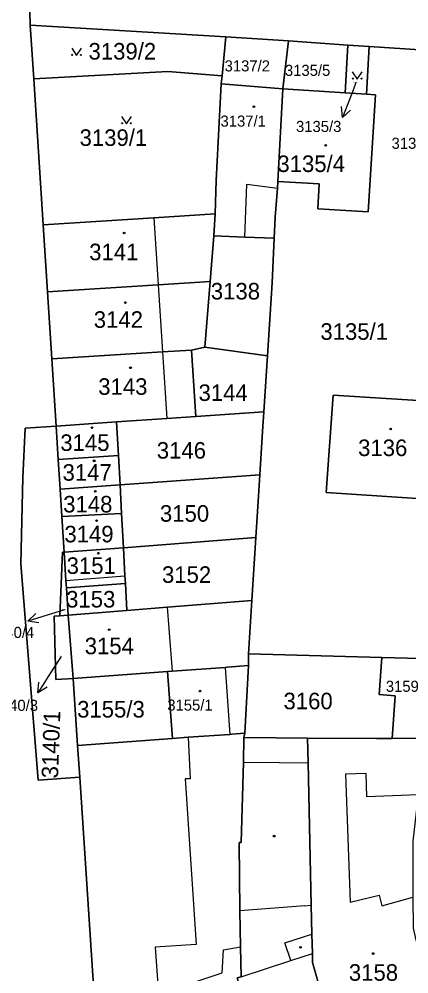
# Model space of a CAD drawing. Extents: x -596233 to -595156, y -1161235 to -1159375.
# Drawn here: x -595617.7 to -595577.7, y -1161038.8 to -1160940.7 of the extents above; entities that cross this region are included whole.
import ezdxf

# ---------------------------------------------------------------- set-up
doc = ezdxf.new("R2010")
doc.units = 0
for name, color, linetype in [('KN_CAR_KR', 7, 'Continuous'), ('KN_KULTURY', 7, 'Continuous'), ('KN_PARC_CIS_POM', 7, 'Continuous'), ('KN_PARC_CIS_POZ', 7, 'Continuous'), ('KN_PARC_CIS_STAV', 7, 'Continuous'), ('KN_PARC_PLOCHA', 7, 'Continuous'), ('PARC_C_SIPKA', 7, 'Continuous'), ('parcely_l', 7, 'Continuous')]:
    doc.layers.add(name, color=color, linetype=linetype)

msp = doc.modelspace()

# ---------------------------------------------------------------- linework, layer by layer
at = {"layer": 'KN_CAR_KR'}
for points in [[(-595594.53, -1160963.12), (-595594.34, -1160957.7)], [(-595594.34, -1160957.7), (-595591.19, -1160958.09)], [(-595603.88, -1160961.14), (-595603.44, -1160968.03)], [(-595603.44, -1160968.03), (-595603, -1160974.92)], [(-595603, -1160974.92), (-595602.57, -1160981.75)], [(-595612.93, -1160998.39), (-595606.86, -1160997.92)], [(-595602.52, -1161001.14), (-595602.01, -1161007.7)], [(-595596.56, -1161007.33), (-595596.08, -1161014.2)], [(-595600.35, -1161014.49), (-595600.16, -1161018.74)], [(-595594.67, -1161017.04), (-595591.02, -1161017.08)], [(-595591.02, -1161017.08), (-595588.04, -1161017.11)], [(-595600.16, -1161018.74), (-595600.66, -1161018.77)], [(-595600.66, -1161018.77), (-595599.55, -1161035.76)], [(-595582.08, -1161018.2), (-595584.21, -1161018.28)], [(-595584.21, -1161018.28), (-595583.71, -1161031.42)], [(-595581.99, -1161020.61), (-595582.08, -1161018.2)], [(-595576.71, -1161020.41), (-595581.99, -1161020.61)], [(-595583.71, -1161031.42), (-595580.74, -1161030.7)], [(-595580.74, -1161030.7), (-595580.45, -1161031.8)], [(-595580.45, -1161031.8), (-595577.28, -1161030.89)], [(-595588.38, -1161031.78), (-595595.05, -1161032.3)], [(-595588.38, -1161031.78), (-595587.71, -1161031.73)], [(-595590.42, -1161035.6), (-595588.52, -1161034.98)], [(-595588.52, -1161034.98), (-595587.64, -1161034.69)], [(-595599.55, -1161035.76), (-595603.74, -1161036.04)], [(-595603.74, -1161036.04), (-595603.42, -1161040.86)], [(-595596.86, -1161038.66), (-595596.75, -1161036.32)], [(-595596.75, -1161036.32), (-595594.98, -1161036)], [(-595589.82, -1161037.41), (-595590.42, -1161035.6)], [(-595594.92, -1161039.08), (-595589.82, -1161037.41)], [(-595589.82, -1161037.41), (-595587.6, -1161036.68)], [(-595603.42, -1161040.86), (-595596.86, -1161038.66)]]:
    msp.add_lwpolyline(points, dxfattribs=at)
at = {"layer": 'KN_KULTURY'}
for points in [[(-595612.3318, -1160943.7116), (-595611.8318, -1160944.4616), (-595611.3318, -1160943.7116)], [(-595583.4918, -1160946.1516), (-595582.9918, -1160946.9016), (-595582.4918, -1160946.1516)], [(-595607.2018, -1160950.7316), (-595606.7018, -1160951.4816), (-595606.2018, -1160950.7316)]]:
    msp.add_lwpolyline(points, dxfattribs=at)
for centre, radius in [((-595612.282, -1160944.4114), 0.05), ((-595611.3826, -1160944.4114), 0.05), ((-595583.442, -1160946.8514), 0.05), ((-595582.5426, -1160946.8514), 0.05), ((-595593.61, -1160949.73), 0.09), ((-595593.61, -1160949.73), 0.0398), ((-595607.152, -1160951.4314), 0.05), ((-595606.2526, -1160951.4314), 0.05), ((-595586.23, -1160953.7), 0.09), ((-595586.23, -1160953.7), 0.0398), ((-595606.95, -1160962.7), 0.09), ((-595606.95, -1160962.7), 0.0398), ((-595606.82, -1160969.85), 0.09), ((-595606.82, -1160969.85), 0.0398), ((-595606.29, -1160976.54), 0.09), ((-595606.29, -1160976.54), 0.0398), ((-595610.25, -1160982.69), 0.09), ((-595610.25, -1160982.69), 0.0398), ((-595579.55, -1160982.83), 0.09), ((-595579.55, -1160982.83), 0.0398), ((-595610.03, -1160986.1), 0.09), ((-595610.03, -1160986.1), 0.0398), ((-595609.91, -1160989.23), 0.09), ((-595609.91, -1160989.23), 0.0398), ((-595609.77, -1160992.24), 0.09), ((-595609.77, -1160992.24), 0.0398), ((-595609.6, -1160995.59), 0.09), ((-595609.6, -1160995.59), 0.0398), ((-595608.48, -1161003.44), 0.09), ((-595608.48, -1161003.44), 0.0398), ((-595599.15, -1161009.74), 0.09), ((-595599.15, -1161009.74), 0.0398), ((-595591.53, -1161024.63), 0.09), ((-595591.53, -1161024.63), 0.0398), ((-595588.83, -1161036.06), 0.09), ((-595588.83, -1161036.06), 0.0398), ((-595581.34, -1161036.7), 0.09), ((-595581.34, -1161036.7), 0.0398)]:
    msp.add_circle(centre, radius, dxfattribs=at)
at = {"layer": 'KN_PARC_PLOCHA'}
for points in [[(-595631.7, -1160897.5), (-595615.14, -1160895.31), (-595616.98, -1160898.71), (-595617.7, -1160902.65), (-595617.29, -1160919.81), (-595617.05, -1160922.72), (-595616.62, -1160941.37), (-595616.22, -1160946.87), (-595615.26, -1160961.87), (-595614.82, -1160968.76), (-595614.38, -1160975.64), (-595613.94, -1160982.53), (-595617.11, -1160982.74), (-595617.35, -1160987.8), (-595617.56, -1160996.69), (-595615.79, -1161018.89), (-595611.5, -1161018.59), (-595609.88, -1161043.14), (-595608.93, -1161050.44), (-595606.83, -1161051.74), (-595620.07, -1161056.19)], [(-595495.5, -1160949.29), (-595504.84, -1160948.66), (-595517.47, -1160947.9), (-595523.68, -1160947.4), (-595529.26, -1160947.06), (-595534.17, -1160946.74), (-595542.8, -1160946.18), (-595552.41, -1160945.52), (-595558.17, -1160945.14), (-595567.75, -1160944.5), (-595571.42, -1160944.26), (-595576.02, -1160943.94), (-595581.75, -1160943.55), (-595583.96, -1160943.4), (-595590.05, -1160942.98), (-595596.48, -1160942.57), (-595616.62, -1160941.37), (-595617.05, -1160922.72)], [(-595575.23, -1161006.44), (-595580.46, -1161006.3), (-595594.18, -1161005.93), (-595593.83, -1161000.44), (-595593.42, -1160993.98), (-595593.14, -1160989.72), (-595593, -1160987.53), (-595592.72, -1160983.09), (-595592.59, -1160981.07), (-595592.22, -1160975.31), (-595591.73, -1160967.81), (-595591.54, -1160963.24), (-595591.41, -1160961.08), (-595591.19, -1160958.09), (-595591.15, -1160957.4), (-595586.89, -1160957.66), (-595587.03, -1160960.22), (-595581.85, -1160960.53), (-595581.11, -1160948.52), (-595582.04, -1160948.46), (-595581.75, -1160943.55), (-595576.02, -1160943.94)], [(-595573.47, -1160980.12), (-595585.46, -1160979.35), (-595586.17, -1160989.36), (-595574.24, -1160990.15)]]:
    msp.add_lwpolyline(points, dxfattribs=at)
for points in [[(-595596.48, -1160942.57), (-595596.88, -1160946.56), (-595602.44, -1160946.12), (-595616.22, -1160946.87), (-595616.62, -1160941.37)], [(-595590.05, -1160942.98), (-595590.63, -1160947.91), (-595596.96, -1160947.37), (-595596.88, -1160946.56), (-595596.48, -1160942.57)], [(-595583.96, -1160943.4), (-595584.24, -1160948.32), (-595590.63, -1160947.91), (-595590.05, -1160942.98)], [(-595581.75, -1160943.55), (-595582.04, -1160948.46), (-595584.24, -1160948.32), (-595583.96, -1160943.4)], [(-595596.88, -1160946.56), (-595596.96, -1160947.37), (-595597.5, -1160957.31), (-595597.59, -1160960.74), (-595603.88, -1160961.14), (-595615.26, -1160961.87), (-595616.22, -1160946.87), (-595602.44, -1160946.12)], [(-595590.63, -1160947.91), (-595591.15, -1160957.4), (-595591.19, -1160958.09), (-595591.41, -1160961.08), (-595591.54, -1160963.24), (-595594.53, -1160963.12), (-595597.73, -1160963), (-595597.59, -1160960.74), (-595597.5, -1160957.31), (-595596.96, -1160947.37)], [(-595584.24, -1160948.32), (-595582.04, -1160948.46), (-595581.11, -1160948.52), (-595581.85, -1160960.53), (-595587.03, -1160960.22), (-595586.89, -1160957.66), (-595591.15, -1160957.4), (-595590.63, -1160947.91)], [(-595597.73, -1160963), (-595598.11, -1160967.69), (-595603.44, -1160968.03), (-595614.82, -1160968.76), (-595615.26, -1160961.87), (-595603.88, -1160961.14), (-595597.59, -1160960.74)], [(-595591.54, -1160963.24), (-595591.73, -1160967.81), (-595592.22, -1160975.31), (-595598.65, -1160974.41), (-595598.11, -1160967.69), (-595597.73, -1160963), (-595594.53, -1160963.12)], [(-595598.65, -1160974.41), (-595600.01, -1160974.73), (-595603, -1160974.92), (-595614.38, -1160975.64), (-595614.82, -1160968.76), (-595603.44, -1160968.03), (-595598.11, -1160967.69)], [(-595599.57, -1160981.55), (-595602.57, -1160981.75), (-595607.72, -1160982.11), (-595613.94, -1160982.53), (-595614.38, -1160975.64), (-595603, -1160974.92), (-595600.01, -1160974.73)], [(-595592.22, -1160975.31), (-595592.59, -1160981.07), (-595599.57, -1160981.55), (-595600.01, -1160974.73), (-595598.65, -1160974.41)], [(-595573.47, -1160980.12), (-595574.24, -1160990.15), (-595586.17, -1160989.36), (-595585.46, -1160979.35)], [(-595593, -1160987.53), (-595607.37, -1160988.56), (-595607.53, -1160985.54), (-595607.72, -1160982.11), (-595602.57, -1160981.75), (-595599.57, -1160981.55), (-595592.59, -1160981.07), (-595592.72, -1160983.09)], [(-595613.72, -1160985.97), (-595613.53, -1160989), (-595613.35, -1160991.82), (-595613.11, -1160995.48), (-595613.28, -1160995.49), (-595613.54, -1161002.02), (-595614.13, -1161002.06), (-595613.98, -1161008.57), (-595612.2, -1161008.44), (-595611.73, -1161015.32), (-595611.5, -1161018.59), (-595615.79, -1161018.89), (-595617.56, -1160996.69), (-595617.35, -1160987.8), (-595617.11, -1160982.74), (-595613.94, -1160982.53)], [(-595607.53, -1160985.54), (-595613.72, -1160985.97), (-595613.94, -1160982.53), (-595607.72, -1160982.11)], [(-595607.37, -1160988.56), (-595613.53, -1160989), (-595613.72, -1160985.97), (-595607.53, -1160985.54)], [(-595593.42, -1160993.98), (-595607.02, -1160995.02), (-595607.21, -1160991.51), (-595607.37, -1160988.56), (-595593, -1160987.53), (-595593.14, -1160989.72)], [(-595607.21, -1160991.51), (-595613.35, -1160991.82), (-595613.53, -1160989), (-595607.37, -1160988.56)], [(-595607.02, -1160995.02), (-595613.11, -1160995.48), (-595613.35, -1160991.82), (-595607.21, -1160991.51)], [(-595593.83, -1161000.44), (-595602.52, -1161001.14), (-595606.67, -1161001.47), (-595606.82, -1160998.68), (-595606.86, -1160997.92), (-595607.02, -1160995.02), (-595593.42, -1160993.98)], [(-595606.82, -1160998.68), (-595612.88, -1160999.15), (-595612.93, -1160998.39), (-595613.11, -1160995.48), (-595607.02, -1160995.02), (-595606.86, -1160997.92)], [(-595612.88, -1160999.15), (-595612.7, -1161001.95), (-595613.54, -1161002.02), (-595613.28, -1160995.49), (-595613.11, -1160995.48), (-595612.93, -1160998.39)], [(-595606.67, -1161001.47), (-595612.7, -1161001.95), (-595612.88, -1160999.15), (-595606.82, -1160998.68)], [(-595594.18, -1161005.93), (-595594.16, -1161007.13), (-595596.37, -1161007.29), (-595596.56, -1161007.33), (-595602.01, -1161007.7), (-595602.48, -1161007.73), (-595612.2, -1161008.44), (-595612.7, -1161001.95), (-595606.67, -1161001.47), (-595602.52, -1161001.14), (-595593.83, -1161000.44)], [(-595612.2, -1161008.44), (-595613.98, -1161008.57), (-595614.13, -1161002.06), (-595613.54, -1161002.02), (-595612.7, -1161001.95)], [(-595580.46, -1161006.3), (-595580.73, -1161010.11), (-595579.09, -1161010.23), (-595579.4, -1161014.6), (-595581.01, -1161014.6), (-595588.1, -1161014.59), (-595594.63, -1161014.5), (-595594.54, -1161014.06), (-595594.16, -1161007.13), (-595594.18, -1161005.93)], [(-595575.23, -1161006.44), (-595575.35, -1161008.11), (-595576.23, -1161014.59), (-595579.4, -1161014.6), (-595579.09, -1161010.23), (-595580.73, -1161010.11), (-595580.46, -1161006.3)], [(-595601.96, -1161014.6), (-595611.73, -1161015.32), (-595612.2, -1161008.44), (-595602.48, -1161007.73)], [(-595594.54, -1161014.06), (-595595.88, -1161014.16), (-595596.08, -1161014.2), (-595600.35, -1161014.49), (-595601.96, -1161014.6), (-595602.48, -1161007.73), (-595602.01, -1161007.7), (-595596.56, -1161007.33), (-595596.37, -1161007.29), (-595594.16, -1161007.13)], [(-595594.63, -1161014.5), (-595594.67, -1161017.04), (-595594.93, -1161025.3), (-595595.13, -1161025.3), (-595595.05, -1161032.3), (-595594.98, -1161036), (-595594.92, -1161039.08), (-595595.34, -1161039.19), (-595592.98, -1161046.93), (-595606.83, -1161051.74), (-595608.93, -1161050.44), (-595609.88, -1161043.14), (-595611.5, -1161018.59), (-595611.73, -1161015.32), (-595601.96, -1161014.6), (-595600.35, -1161014.49), (-595596.08, -1161014.2), (-595595.88, -1161014.16), (-595594.54, -1161014.06)], [(-595588.1, -1161014.59), (-595588.04, -1161017.11), (-595587.71, -1161031.73), (-595587.64, -1161034.69), (-595587.6, -1161036.68), (-595587.58, -1161037.63), (-595585.63, -1161044.42), (-595592.98, -1161046.93), (-595595.34, -1161039.19), (-595594.92, -1161039.08), (-595594.98, -1161036), (-595595.05, -1161032.3), (-595595.13, -1161025.3), (-595594.93, -1161025.3), (-595594.67, -1161017.04), (-595594.63, -1161014.5)], [(-595575.09, -1161041.45), (-595575.05, -1161041.61), (-595578.35, -1161042.58), (-595578.4, -1161042.42), (-595585.63, -1161044.42), (-595587.58, -1161037.63), (-595587.6, -1161036.68), (-595587.64, -1161034.69), (-595587.71, -1161031.73), (-595588.04, -1161017.11), (-595588.1, -1161014.59), (-595581.01, -1161014.6), (-595579.4, -1161014.6), (-595576.23, -1161014.59), (-595575.98, -1161014.59), (-595576.16, -1161015.95), (-595576.54, -1161018.87), (-595576.66, -1161019.95), (-595576.71, -1161020.41), (-595577.27, -1161025.17), (-595577.28, -1161030.89), (-595577.24, -1161034.09), (-595576.99, -1161035.16)]]:
    msp.add_lwpolyline(points, close=True, dxfattribs=at)
at = {"layer": 'PARC_C_SIPKA'}
for points in [[(-595583.12, -1160947.25), (-595583.4, -1160948.05), (-595584.4967, -1160950.8423)], [(-595583.6658, -1160950.0944), (-595584.4967, -1160950.8423), (-595584.5965, -1160949.7288)], [(-595613.09, -1161001.41), (-595613.96, -1161001.68), (-595616.8275, -1161002.5617)], [(-595615.7247, -1161002.7457), (-595616.8275, -1161002.5617), (-595616.0186, -1161001.7899)], [(-595613.42, -1161006.19), (-595614.2, -1161007.4), (-595615.8233, -1161009.9229)], [(-595614.8617, -1161009.3525), (-595615.8233, -1161009.9229), (-595615.7027, -1161008.8114)]]:
    msp.add_lwpolyline(points, dxfattribs=at)
at = {"layer": 'parcely_l'}
for points in [[(-595616.62, -1160941.37), (-595617.05, -1160922.72)], [(-595596.48, -1160942.57), (-595616.62, -1160941.37)], [(-595616.22, -1160946.87), (-595616.62, -1160941.37)], [(-595596.88, -1160946.56), (-595596.48, -1160942.57)], [(-595596.48, -1160942.57), (-595590.05, -1160942.98)], [(-595590.05, -1160942.98), (-595590.63, -1160947.91)], [(-595583.96, -1160943.4), (-595590.05, -1160942.98)], [(-595584.24, -1160948.32), (-595583.96, -1160943.4)], [(-595581.75, -1160943.55), (-595583.96, -1160943.4)], [(-595581.75, -1160943.55), (-595582.04, -1160948.46)], [(-595576.02, -1160943.94), (-595581.75, -1160943.55)], [(-595616.22, -1160946.87), (-595602.44, -1160946.12), (-595596.88, -1160946.56)], [(-595615.26, -1160961.87), (-595616.22, -1160946.87)], [(-595596.88, -1160946.56), (-595596.96, -1160947.37)], [(-595596.96, -1160947.37), (-595597.5, -1160957.31), (-595597.59, -1160960.74)], [(-595590.63, -1160947.91), (-595596.96, -1160947.37)], [(-595591.15, -1160957.4), (-595590.63, -1160947.91)], [(-595590.63, -1160947.91), (-595584.24, -1160948.32)], [(-595582.04, -1160948.46), (-595581.11, -1160948.52), (-595581.85, -1160960.53), (-595587.03, -1160960.22), (-595586.89, -1160957.66), (-595591.15, -1160957.4)], [(-595584.24, -1160948.32), (-595582.04, -1160948.46)], [(-595591.15, -1160957.4), (-595591.19, -1160958.09), (-595591.41, -1160961.08), (-595591.54, -1160963.24)], [(-595615.26, -1160961.87), (-595603.88, -1160961.14), (-595597.59, -1160960.74)], [(-595597.59, -1160960.74), (-595597.73, -1160963)], [(-595614.82, -1160968.76), (-595615.26, -1160961.87)], [(-595597.73, -1160963), (-595598.11, -1160967.69)], [(-595591.54, -1160963.24), (-595594.53, -1160963.12), (-595597.73, -1160963)], [(-595591.54, -1160963.24), (-595591.73, -1160967.81), (-595592.22, -1160975.31)], [(-595598.11, -1160967.69), (-595603.44, -1160968.03), (-595614.82, -1160968.76)], [(-595598.11, -1160967.69), (-595598.65, -1160974.41)], [(-595614.38, -1160975.64), (-595614.82, -1160968.76)], [(-595600.01, -1160974.73), (-595603, -1160974.92), (-595614.38, -1160975.64)], [(-595598.65, -1160974.41), (-595600.01, -1160974.73)], [(-595599.57, -1160981.55), (-595600.01, -1160974.73)], [(-595598.65, -1160974.41), (-595592.22, -1160975.31)], [(-595614.38, -1160975.64), (-595613.94, -1160982.53)], [(-595592.22, -1160975.31), (-595592.59, -1160981.07)], [(-595574.24, -1160990.15), (-595586.17, -1160989.36), (-595585.46, -1160979.35), (-595573.47, -1160980.12)], [(-595607.72, -1160982.11), (-595602.57, -1160981.75), (-595599.57, -1160981.55)], [(-595599.57, -1160981.55), (-595592.59, -1160981.07)], [(-595592.59, -1160981.07), (-595592.72, -1160983.09), (-595593, -1160987.53)], [(-595611.5, -1161018.59), (-595615.79, -1161018.89), (-595617.56, -1160996.69), (-595617.35, -1160987.8), (-595617.11, -1160982.74), (-595613.94, -1160982.53)], [(-595613.94, -1160982.53), (-595607.72, -1160982.11)], [(-595613.94, -1160982.53), (-595613.72, -1160985.97)], [(-595607.53, -1160985.54), (-595607.72, -1160982.11)], [(-595613.72, -1160985.97), (-595607.53, -1160985.54)], [(-595607.37, -1160988.56), (-595607.53, -1160985.54)], [(-595613.72, -1160985.97), (-595613.53, -1160989)], [(-595593, -1160987.53), (-595607.37, -1160988.56)], [(-595593.42, -1160993.98), (-595593.14, -1160989.72), (-595593, -1160987.53)], [(-595607.37, -1160988.56), (-595613.53, -1160989)], [(-595613.53, -1160989), (-595613.35, -1160991.82)], [(-595607.37, -1160988.56), (-595607.21, -1160991.51)], [(-595607.21, -1160991.51), (-595613.35, -1160991.82)], [(-595613.35, -1160991.82), (-595613.11, -1160995.48)], [(-595607.21, -1160991.51), (-595607.02, -1160995.02)], [(-595607.02, -1160995.02), (-595593.42, -1160993.98)], [(-595593.42, -1160993.98), (-595593.83, -1161000.44)], [(-595613.11, -1160995.48), (-595607.02, -1160995.02)], [(-595607.02, -1160995.02), (-595606.86, -1160997.92), (-595606.82, -1160998.68)], [(-595613.11, -1160995.48), (-595613.28, -1160995.49), (-595613.54, -1161002.02)], [(-595612.88, -1160999.15), (-595612.93, -1160998.39), (-595613.11, -1160995.48)], [(-595606.82, -1160998.68), (-595612.88, -1160999.15)], [(-595612.7, -1161001.95), (-595612.88, -1160999.15)], [(-595606.67, -1161001.47), (-595606.82, -1160998.68)], [(-595593.83, -1161000.44), (-595602.52, -1161001.14), (-595606.67, -1161001.47)], [(-595593.83, -1161000.44), (-595594.18, -1161005.93)], [(-595612.2, -1161008.44), (-595613.98, -1161008.57), (-595614.13, -1161002.06), (-595613.54, -1161002.02)], [(-595613.54, -1161002.02), (-595612.7, -1161001.95)], [(-595606.67, -1161001.47), (-595612.7, -1161001.95)], [(-595612.7, -1161001.95), (-595612.2, -1161008.44)], [(-595594.16, -1161007.13), (-595594.18, -1161005.93)], [(-595594.18, -1161005.93), (-595580.46, -1161006.3)], [(-595580.46, -1161006.3), (-595580.73, -1161010.11), (-595579.09, -1161010.23), (-595579.4, -1161014.6)], [(-595580.46, -1161006.3), (-595575.23, -1161006.44)], [(-595612.2, -1161008.44), (-595602.48, -1161007.73)], [(-595594.16, -1161007.13), (-595596.37, -1161007.29), (-595596.56, -1161007.33), (-595602.01, -1161007.7), (-595602.48, -1161007.73)], [(-595602.48, -1161007.73), (-595601.96, -1161014.6)], [(-595594.54, -1161014.06), (-595594.16, -1161007.13)], [(-595612.2, -1161008.44), (-595611.73, -1161015.32)], [(-595601.96, -1161014.6), (-595611.73, -1161015.32)], [(-595601.96, -1161014.6), (-595600.35, -1161014.49), (-595596.08, -1161014.2), (-595595.88, -1161014.16), (-595594.54, -1161014.06)], [(-595594.63, -1161014.5), (-595594.67, -1161017.04), (-595594.93, -1161025.3), (-595595.13, -1161025.3), (-595595.05, -1161032.3), (-595594.98, -1161036), (-595594.92, -1161039.08), (-595595.34, -1161039.19), (-595592.98, -1161046.93)], [(-595594.54, -1161014.06), (-595594.63, -1161014.5)], [(-595588.1, -1161014.59), (-595594.63, -1161014.5)], [(-595579.4, -1161014.6), (-595581.01, -1161014.6), (-595588.1, -1161014.59)], [(-595585.63, -1161044.42), (-595587.58, -1161037.63), (-595587.6, -1161036.68), (-595587.64, -1161034.69), (-595587.71, -1161031.73), (-595588.04, -1161017.11), (-595588.1, -1161014.59)], [(-595579.4, -1161014.6), (-595576.23, -1161014.59)], [(-595611.73, -1161015.32), (-595611.5, -1161018.59)], [(-595606.83, -1161051.74), (-595608.93, -1161050.44), (-595609.88, -1161043.14), (-595611.5, -1161018.59)]]:
    msp.add_lwpolyline(points, dxfattribs=at)

# ---------------------------------------------------------------- texts
at = {"layer": 'KN_PARC_CIS_POM'}
for s, p in [('3135/3', (-595583.4033, -1160947.25)), ('3140/4', (-595613.3733, -1161001.41)), ('3140/3', (-595613.7033, -1161006.19))]:
    msp.add_text(s, height=0.1, dxfattribs=at).set_placement(p)
at = {"layer": 'KN_PARC_CIS_POZ'}
for s, height, p in [('3139/2', 1.7, (-595610.6066, -1160944.89)), ('3137/2', 1.14, (-595596.62, -1160946.11)), ('3135/5', 1.14, (-595590.42, -1160946.57)), ('3135/3', 1.14, (-595589.28, -1160952.33)), ('3139/1', 1.7, (-595611.5266, -1160953.76)), ('3135/2', 1.14, (-595579.46, -1160954.06)), ('3138', 1.7, (-595598.0366, -1160969.53)), ('3135/1', 1.7, (-595586.7766, -1160973.67)), ('3144', 1.7, (-595599.2966, -1160979.95)), ('3146', 1.7, (-595603.5866, -1160985.87)), ('3150', 1.7, (-595603.2666, -1160992.35)), ('3152', 1.7, (-595603.0566, -1160998.63)), ('3153', 1.7, (-595612.9066, -1161001.16)), ('3140/4', 1.14, (-595620.8505, -1161004.2893)), ('3159', 1.14, (-595580.05, -1161009.82)), ('3160', 1.7, (-595590.5666, -1161011.61)), ('3140/3', 1.14, (-595620.46, -1161011.78)), ('3155/3', 1.7, (-595611.7766, -1161012.46))]:
    msp.add_text(s, height=height, dxfattribs=at).set_placement(p)
msp.add_text('3140/1', height=1.7, rotation=88.002068, dxfattribs=at).set_placement((-595613.7379, -1161018.7237))
at = {"layer": 'KN_PARC_CIS_STAV'}
for s, height, p in [('3137/1', 1.14, (-595597.04, -1160951.78)), ('3135/4', 1.7, (-595591.1966, -1160956.44)), ('3141', 1.7, (-595610.5366, -1160965.5)), ('3142', 1.7, (-595610.0666, -1160972.44)), ('3143', 1.7, (-595609.6066, -1160979.32)), ('3145', 1.7, (-595613.5066, -1160985.08)), ('3136', 1.7, (-595582.8966, -1160985.61)), ('3147', 1.7, (-595613.2766, -1160988.14)), ('3148', 1.7, (-595613.2066, -1160991.4)), ('3149', 1.7, (-595613.0866, -1160994.47)), ('3151', 1.7, (-595612.8566, -1160997.71)), ('3154', 1.7, (-595610.9966, -1161005.96)), ('3155/1', 1.14, (-595602.51, -1161011.75)), ('3158', 1.7, (-595583.8466, -1161039.49))]:
    msp.add_text(s, height=height, dxfattribs=at).set_placement(p)

doc.saveas('drawing.dxf')
